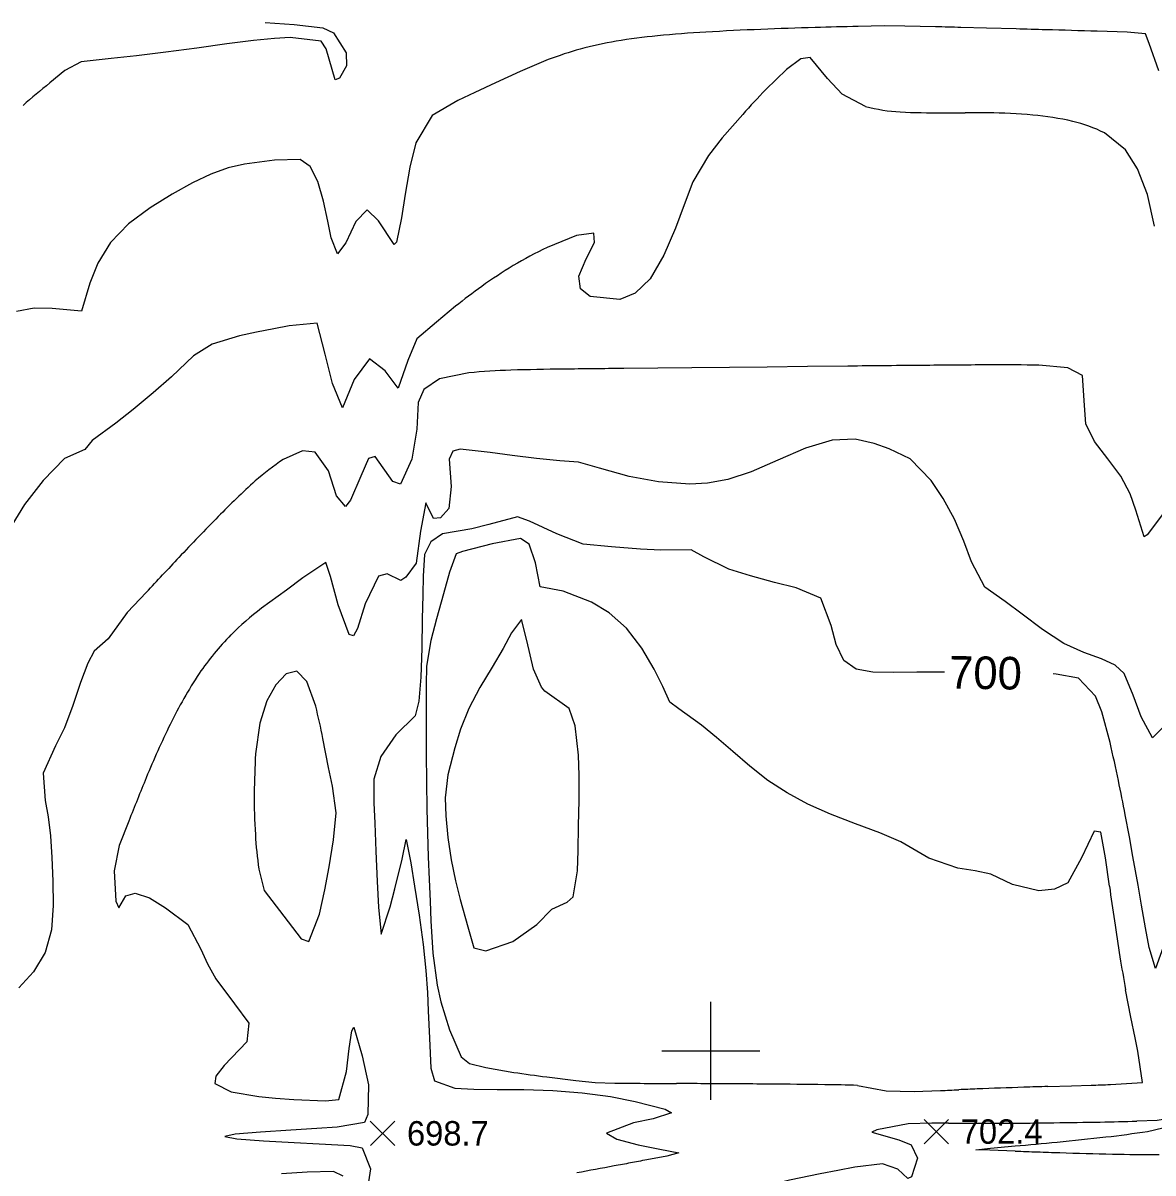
# Model space of a CAD drawing. Extents: x 2566079 to 2571326, y 424054 to 426896.
# Drawn here: x 2566578 to 2567271, y 424925 to 425631 of the extents above; entities that cross this region are included whole.
import ezdxf

# ---------------------------------------------------------------- set-up
doc = ezdxf.new("R2010")
doc.units = 0
for name, color, linetype in [('Contour_ADS_Label_Major', 7, 'Continuous'), ('Contour_ADS_Major', 7, 'Continuous'), ('Contour_ADS_Minor', 7, 'Continuous'), ('Contour_ADS_Spot_Elevation', 7, 'Continuous'), ('Contour_ADS_Tick', 7, 'Continuous')]:
    doc.layers.add(name, color=color, linetype=linetype)

# ---------------------------------------------------------------- blocks, each defined once
blk = doc.blocks.new('S890')
at = {"layer": 'Contour_ADS_Tick'}
for p, q in [((0, -0.5), (0, 0.5)), ((-0.5, 0), (0.5, 0))]:
    blk.add_line(p, q, dxfattribs=at)
blk = doc.blocks.new('S750')
at = {"layer": 'Contour_ADS_Spot_Elevation'}
for p, q in [((-0.5, 0.498), (0.5, -0.498)), ((-0.498, -0.5), (0.498, 0.5))]:
    blk.add_line(p, q, dxfattribs=at)

msp = doc.modelspace()

# ---------------------------------------------------------------- linework, layer by layer
at = {"layer": 'Contour_ADS_Major'}
for points in [[(2566726.44, 425630.92), (2566744.39, 425629.75), (2566761.94, 425627.82), (2566768.5, 425624.68), (2566776.31, 425612.3), (2566776.46, 425604.34), (2566772.04, 425596.78), (2566769.46, 425595.77), (2566764.01, 425614.94), (2566760.9, 425619.46), (2566741.87, 425621.82), (2566732.19, 425621.21), (2566719.3, 425619.91), (2566703.05, 425617.83), (2566684.65, 425615.31), (2566665.65, 425612.77), (2566647.59, 425610.59), (2566632, 425608.85), (2566613.63, 425606.79), (2566603.62, 425601.53), (2566594.32, 425593.88)], [(2567143.42, 425232.39), (2567142.83, 425232.39), (2567126.47, 425232.29), (2567111.9, 425232.14), (2567099.34, 425232.29), (2567089.13, 425234.18), (2567081.63, 425239.56), (2567076.91, 425249.32), (2567073.89, 425261), (2567067.55, 425277.73), (2567052.32, 425284.1), (2567039.07, 425287.44), (2567024.27, 425291.39), (2567011.04, 425295.55), (2566995.66, 425303.1), (2566987.93, 425307.51), (2566969.32, 425307.23), (2566956.79, 425307.76), (2566938.98, 425309.26), (2566921.63, 425310.99), (2566905.57, 425317.18), (2566888.76, 425325.1), (2566881.32, 425327.63), (2566863.83, 425323.05), (2566853.39, 425320.26), (2566835.3, 425317.15), (2566828.21, 425312.4), (2566824.2, 425304.54), (2566823.49, 425291.28), (2566823.17, 425279.73), (2566822.88, 425264.81), (2566822.59, 425247.05), (2566822, 425229.21), (2566820.75, 425214.58), (2566818.65, 425205.61), (2566806.79, 425193.97), (2566797.46, 425180.71), (2566793.28, 425166.74), (2566793.29, 425152.22), (2566793.77, 425139.67), (2566794.45, 425122.48), (2566795.22, 425103.88), (2566795.98, 425088.07), (2566797.72, 425071.69), (2566803.16, 425088.28), (2566806.13, 425099.33), (2566810.5, 425117.62), (2566813.11, 425129.77), (2566815.89, 425115.45), (2566818.25, 425101.07), (2566821.04, 425083.3), (2566823.53, 425065.2), (2566825.17, 425049.23), (2566826.1, 425035.74), (2566826.63, 425024.49), (2566827.37, 425007.83), (2566828.21, 424989.43), (2566830.37, 424981.63), (2566842.96, 424977.12), (2566854.51, 424976.51), (2566868.85, 424976.38), (2566885.31, 424976.24), (2566903.02, 424975.68), (2566921.06, 424974.3), (2566938.39, 424971.89), (2566953.58, 424968.98), (2566971.94, 424964.3), (2566975.81, 424961.99), (2566964.6, 424958.32), (2566952.45, 424955.91), (2566935.89, 424949.4), (2566942.26, 424945.74), (2566955.41, 424942.35), (2566968.71, 424939.7), (2566980.36, 424937.4), (2566972.94, 424935.36), (2566960.63, 424933.08)], [(2566757.54, 425211.41), (2566752.16, 425226.73), (2566745.93, 425232.98), (2566739.35, 425231.4), (2566733.04, 425224.64), (2566727.56, 425214.74), (2566723.3, 425201.03), (2566720.62, 425182.19), (2566720.62, 425182.19)], [(2567244.96, 425189.11), (2567240.01, 425208.04), (2567236.07, 425217.72), (2567225.66, 425228.76), (2567211.81, 425231.21), (2567210.08, 425231.29)], [(2566722.68, 425111.49), (2566725.91, 425098.32), (2566738.05, 425082.69), (2566748.58, 425068.74), (2566753.3, 425067.1), (2566759.92, 425083.86), (2566763.22, 425098.83), (2566765.88, 425112.88), (2566768.55, 425129.38), (2566770.11, 425146.13), (2566767.77, 425162.44), (2566765.35, 425173.87), (2566761.94, 425191.73)], [(2567329.12, 425145.83), (2567324.53, 425131.31), (2567319.01, 425116.32), (2567310.81, 425099.77), (2567304.32, 425085.2), (2567298.68, 425066.93), (2567296.97, 425065.26), (2567287, 425081.24), (2567278.53, 425066.56), (2567272.79, 425050.6), (2567268.93, 425063.35), (2567266.79, 425075.48), (2567264.35, 425089.33), (2567262.15, 425101.66), (2567258.93, 425119.34), (2567256.9, 425131.23), (2567254.31, 425144.82)]]:
    msp.add_lwpolyline(points, dxfattribs=at)
for centre, radius, start, end in [((2567135.74, 424935.15), 852.68, 129.41718, 130.8578), ((2566386.09, 425118.03), 383.01, 11.09426, 14.11128), ((2566333.83, 424976.68), 935.56, 11.66283, 13.12386), ((2567463.35, 425143.37), 743.74, 177.00782, 178.87264), ((2565807.82, 424864.24), 1473.46, 10.97759, 11.81021), ((2567070.74, 425155.99), 350.99, 179.67234, 183.81002), ((2566947.79, 425145.15), 227.61, 183.14245, 188.50367), ((2567959.66, 419478.51), 5545.3, 100.5879, 100.82923), ((2568351.49, 417377.12), 7682.9, 100.505369, 100.580769), ((2571254.73, 401707.86), 23618.85, 100.475086, 100.499608)]:
    msp.add_arc(centre, radius, start, end, dxfattribs=at)
at = {"layer": 'Contour_ADS_Minor'}
msp.add_line((2566739.59, 425282.7), (2566724.21, 425271.58), dxfattribs=at)
for points in [[(2567137.83, 425628.37), (2567119, 425628.84), (2567106.35, 425628.91), (2567090.32, 425628.6)], [(2567187.34, 425627.03), (2567169.06, 425627.53), (2567153.44, 425627.95)], [(2567274.88, 425601.39), (2567269.04, 425618.18), (2567266.65, 425623.97), (2567255.56, 425625.02), (2567237.07, 425625.63)], [(2566900.26, 425608.21), (2566882.94, 425600.93), (2566867.93, 425593.93), (2566855.24, 425588.08), (2566844.68, 425583.15), (2566829, 425573.96), (2566818.89, 425557.16), (2566815.28, 425542.32), (2566812.42, 425525.71), (2566810.24, 425511.05), (2566807.16, 425496.2), (2566805.69, 425494.7), (2566796.05, 425509.34), (2566789.19, 425516.11), (2566782.18, 425508.99), (2566775.94, 425495.72), (2566770.99, 425489.07), (2566767.04, 425498.89), (2566764.9, 425509.11), (2566762.28, 425521.43), (2566758.82, 425533.48), (2566754.14, 425542.59), (2566747.97, 425546.88), (2566732.21, 425546.57), (2566713.8, 425544.15), (2566703.81, 425541.82), (2566693.26, 425537.99), (2566681.9, 425532.59), (2566669.44, 425525.69), (2566655.91, 425517.31), (2566642.71, 425507.42), (2566631.56, 425495.96), (2566623.77, 425483.23), (2566618.91, 425471), (2566613.88, 425453.8), (2566595.73, 425455.47), (2566584.84, 425455.66), (2566573.88, 425453.74)], [(2567094.98, 425579.48), (2567080.63, 425587.1), (2567071.66, 425596.68), (2567060.97, 425609.43), (2567055.13, 425608.71), (2567046.4, 425602.17), (2567033.76, 425589.83)], [(2567019.56, 425574.61), (2567007.01, 425560.17), (2566998.56, 425549.37), (2566988.98, 425533.19), (2566983.58, 425519.12), (2566978.27, 425504.76), (2566971.2, 425488.21), (2566962.84, 425473.78), (2566953.66, 425464.85), (2566944.11, 425460.96), (2566925.98, 425462.83), (2566920.01, 425467.6), (2566918.93, 425475.39), (2566923.48, 425485.92), (2566928.71, 425496.02), (2566928.25, 425501.79), (2566917.56, 425500.36), (2566899.5, 425492.95)], [(2567272.24, 425505.93), (2567267.97, 425525.4), (2567261.84, 425541.25), (2567254.34, 425552.81), (2567241.47, 425563.26)], [(2566843.35, 425456.87), (2566831.56, 425447.15), (2566819.53, 425436.95), (2566814.06, 425423.56), (2566808.08, 425406.71), (2566800.08, 425417.22), (2566790.54, 425424.66), (2566781.14, 425412.03), (2566773.93, 425394.56), (2566767.86, 425409.45), (2566763.37, 425427.47), (2566758.52, 425446.46), (2566741.3, 425444.89), (2566731.81, 425443.13), (2566721.14, 425441.05), (2566710.68, 425438.75), (2566693.96, 425433.53), (2566682.56, 425426.41), (2566668.97, 425413.66), (2566657.78, 425403.82), (2566645.43, 425393.52), (2566634.81, 425385.23), (2566620.42, 425374.45), (2566615.9, 425369.07), (2566603.46, 425363.52), (2566590.35, 425349.93), (2566578.9, 425335.29), (2566571.09, 425322.54)], [(2567083.96, 425420.13), (2567059.27, 425419.87), (2567034.58, 425419.61), (2566988.4, 425419.14), (2566946.57, 425418.71)], [(2567279.52, 425332.34), (2567267.72, 425316.68), (2567265.92, 425315.41), (2567260.86, 425331.75), (2567257.33, 425341.84), (2567251.6, 425352.7), (2567243.51, 425363.3), (2567235.36, 425373.8), (2567230.07, 425384.65), (2567229.35, 425395.95), (2567227.99, 425414.49), (2567219.15, 425419), (2567201.23, 425420.72)], [(2566851.47, 425416.02), (2566833.44, 425412.3), (2566823.87, 425405.89), (2566820.37, 425397.77), (2566819.6, 425381.51), (2566816.5, 425362.99), (2566809.66, 425347.64), (2566804.93, 425349.32), (2566794.02, 425364.63), (2566789.9, 425363.49), (2566785.16, 425352.56), (2566778.95, 425337.82), (2566775.79, 425334.1), (2566770.33, 425340.55), (2566765.48, 425355.82), (2566757.22, 425367.36), (2566749.46, 425368.08), (2566737.67, 425362.9)], [(2567283.08, 425204.34), (2567271.05, 425192.14), (2567264.09, 425205.02), (2567259.19, 425218.26), (2567253.55, 425231.5), (2567248.16, 425236.72), (2567239.79, 425240.58), (2567228.94, 425244.43), (2567216.5, 425250.04), (2567203.44, 425258.45), (2567191.03, 425267.87), (2567180.67, 425275.82), (2567168.13, 425284.57), (2567159.9, 425300.09), (2567155.2, 425312.72), (2567149.48, 425326.28), (2567142.53, 425339), (2567135.1, 425349.87), (2567122.21, 425363.23), (2567109.45, 425369.3), (2567100.22, 425372.73), (2567088.53, 425375.23), (2567074.42, 425374.66), (2567058.18, 425369.73), (2567041.1, 425362.35), (2567024.78, 425355.27), (2567010.44, 425350.64), (2566998, 425348.34), (2566987.05, 425347.68), (2566967.91, 425349.1), (2566949.88, 425352.41), (2566931.63, 425357.57), (2566918.73, 425361.13), (2566907.38, 425362.1), (2566892.96, 425363.49), (2566878, 425365.26), (2566864.68, 425367.24), (2566846.11, 425369.24), (2566841.67, 425368.05), (2566839.36, 425363.06), (2566840.61, 425346.23), (2566839.13, 425332.77), (2566834.16, 425327.03), (2566829.75, 425326.59), (2566825.11, 425336.28), (2566821.78, 425318.85), (2566819.15, 425299.15), (2566812.77, 425290.63), (2566809.72, 425288.61), (2566801.42, 425292.6), (2566796.03, 425291.33), (2566787.92, 425274.39), (2566783.11, 425259.19), (2566780.74, 425254.69), (2566777.99, 425255.41), (2566771.36, 425273.62), (2566766.56, 425291.13), (2566763.77, 425299.68), (2566749.67, 425290.26), (2566739.59, 425282.7)], [(2567244.55, 425101.15), (2567242.16, 425118.38), (2567239.2, 425134.17), (2567235.14, 425134.71), (2567227.36, 425118.5), (2567219.12, 425103.13), (2567210.92, 425099.22), (2567201.24, 425098.19), (2567185.13, 425102.08), (2567171.72, 425108.39), (2567162.23, 425110.4), (2567151.64, 425112.09), (2567133.73, 425118.13), (2567116.52, 425128.26), (2567103.68, 425133.74), (2567088.72, 425139.34), (2567073.49, 425145.18), (2567059.49, 425151.39), (2567046.77, 425158.22), (2567035, 425165.93), (2567023.91, 425174.64), (2567013.42, 425183.7), (2567003.49, 425192.31), (2566994.21, 425199.77), (2566980.26, 425209.95), (2566974.9, 425214.02), (2566970.55, 425223.63), (2566965.26, 425234.17), (2566957.71, 425247.01), (2566948.31, 425259.28), (2566937.61, 425268.69), (2566926.75, 425275.24), (2566909.42, 425282.08), (2566895.22, 425284.71), (2566892.46, 425299.35), (2566888.49, 425310.99), (2566883.27, 425314.39), (2566865.79, 425311.05), (2566847.51, 425306.43), (2566843.78, 425304.91), (2566839.7, 425293.64), (2566839.7, 425293.64)], [(2566839.7, 425293.64), (2566835.9, 425280.41), (2566831.72, 425265.02), (2566828.25, 425251.73), (2566825.42, 425236.11), (2566825.33, 425224.68), (2566825.3, 425214.14), (2566825.27, 425199.54), (2566825.3, 425182.44), (2566825.44, 425164.9), (2566825.73, 425148.59), (2566826.13, 425133.47), (2566826.62, 425119.05), (2566827.15, 425105.05), (2566827.69, 425091.81), (2566828.2, 425079.86), (2566829.37, 425059.97), (2566832.16, 425040.29), (2566834.36, 425030.08), (2566839.56, 425012.94), (2566846.84, 424996.26), (2566851.98, 424992.27), (2566861.86, 424989.7), (2566879.04, 424986.81)], [(2566653.65, 425281.4), (2566641.89, 425268.99), (2566630.24, 425252.83), (2566621.6, 425245.34), (2566617.65, 425237.93), (2566613.27, 425226.07), (2566608.49, 425211.85), (2566603.3, 425198.13), (2566597.89, 425187.09), (2566590.36, 425170.34), (2566591.53, 425153.66), (2566593.43, 425143.62), (2566594.79, 425131.87), (2566595.61, 425118.6), (2566596.16, 425104.2), (2566596.45, 425089.12), (2566595.37, 425074.21), (2566591.56, 425060.38), (2566584.3, 425048.46), (2566575.46, 425038.76)], [(2566642.87, 425140.99), (2566636.88, 425125.92), (2566633.81, 425110.42), (2566634.95, 425091.78), (2566636.65, 425087.66), (2566641.1, 425095.03), (2566646.7, 425096.79), (2566655.45, 425093.79), (2566665.38, 425087.82), (2566679.04, 425077.63), (2566687.13, 425062.41), (2566691.2, 425053.43), (2566696.2, 425044.22), (2566707.77, 425028.85), (2566716.52, 425017.08), (2566715.22, 425005.44), (2566701.46, 424990.93), (2566696.18, 424984.53), (2566695.67, 424979.93), (2566705.66, 424974.78), (2566722.6, 424971.91), (2566732.9, 424970.9), (2566744.11, 424970.08), (2566763.52, 424969.34), (2566771.7, 424970.25), (2566776.36, 424987.33), (2566778.04, 425001.44), (2566779.8, 425012.38), (2566780.95, 425014.47), (2566786.1, 424996.98), (2566790.02, 424979.09), (2566789.5, 424960.95), (2566787.42, 424956.1), (2566770.71, 424953.13), (2566758.27, 424952.34), (2566742.21, 424951.4), (2566723.69, 424950.2), (2566708.07, 424948.82), (2566701.83, 424947.38), (2566709.19, 424945.98), (2566725.6, 424944.73), (2566744.28, 424943.7), (2566759.64, 424942.94), (2566778.69, 424941.93), (2566785.98, 424940.52), (2566791.17, 424927.69), (2566788.56, 424910.25)], [(2567245.14, 424979.35), (2567264.96, 424980.62), (2567262.05, 424999.72), (2567260.34, 425007.95), (2567257.75, 425020.69), (2567254.52, 425037.52)], [(2566899.32, 424984.03), (2566917.08, 424981.87), (2566929.01, 424980.68), (2566941.12, 424980.2)], [(2567089.94, 424978.82), (2567107.51, 424975.46), (2567124.78, 424975.01), (2567140.91, 424975.66)], [(2567206.69, 424978.12), (2567221.4, 424978.59), (2567233.27, 424978.97)], [(2567267.96, 424950.61), (2567282.52, 424953.93), (2567288.21, 424956.79), (2567289.19, 424959.98), (2567273.93, 424957.24), (2567261.38, 424956.83)], [(2567135.59, 424955.58), (2567121.03, 424955.31), (2567101.89, 424951.58), (2567098.74, 424950.18), (2567115.43, 424945.39), (2567123.01, 424942.33), (2567126.82, 424934.16), (2567123.13, 424922.75), (2567120.87, 424921.67), (2567114.66, 424927.34), (2567105.41, 424930.73), (2567088.41, 424928.68), (2567077.97, 424926.62), (2567067.09, 424924.45), (2567048.2, 424920.68), (2567033.27, 424916.95), (2567023.81, 424913.57), (2567012.1, 424903.18), (2566999.26, 424893.79), (2566986.41, 424884.54), (2566971.69, 424874.69), (2566958.06, 424864.54), (2566944.29, 424852.07)], [(2567186.76, 424938.46), (2567171.19, 424938.99), (2567162.5, 424939.31), (2567171.6, 424940.3), (2567186.67, 424941.64)], [(2566774.42, 424923.13), (2566768.42, 424926.01), (2566752.23, 424925.63), (2566736.54, 424924.63)]]:
    msp.add_lwpolyline(points, dxfattribs=at)
msp.add_lwpolyline([(2566896.02, 425223.22), (2566891.12, 425234.16), (2566887.18, 425251.85), (2566883.84, 425264.58), (2566877.74, 425256.58), (2566872.57, 425246.84), (2566865.73, 425235.35), (2566858.24, 425222.88), (2566851.46, 425210.02), (2566846.41, 425197.4), (2566842.9, 425185.89), (2566838.63, 425169.38), (2566837.04, 425155.17), (2566837.42, 425144.12), (2566838.62, 425130.89), (2566840.61, 425117.13), (2566843.3, 425104.27), (2566846.24, 425092.91), (2566850.81, 425076.12), (2566854.62, 425063.29), (2566861.83, 425061.37), (2566878.57, 425067.03), (2566893.28, 425077.59), (2566902.4, 425087.03), (2566911.86, 425091.17), (2566915.5, 425094.52), (2566918.26, 425110.44), (2566918.51, 425122.95), (2566918.81, 425137.97), (2566919.1, 425153.89), (2566919.15, 425168.87), (2566918.81, 425181.41), (2566916.82, 425199.37), (2566913.12, 425210), (2566898.15, 425220.7), (2566896.02, 425223.22)], close=True, dxfattribs=at)
for centre, radius, start, end in [((2567168.52, 422185.7), 3443.78, 91.30114, 91.74002), ((2566790.91, 412444.04), 13188.89, 88.424861, 88.4927), ((2567006.79, 425222.81), 401.95, 95.65334, 99.29269), ((2567045.23, 424808.64), 817.89, 93.39026, 95.47508), ((2567097.96, 423897.08), 1730.97, 92.22481, 93.34826), ((2567153.99, 422549.64), 3079.58, 91.67551, 92.29338), ((2566494.23, 399952.62), 25683.76, 88.412822, 88.453617), ((2566771.35, 409901.08), 15731.44, 88.303528, 88.418119), ((2566981.52, 425394.98), 228.19, 105.67597, 110.86035), ((2566983.38, 425376.2), 246.79, 99.68013, 104.91422), ((2567382.89, 425249.86), 487.31, 135.76188, 138.20946), ((2567123.55, 425690.06), 114.21, 255.51134, 266.26794), ((2567143.3, 426271.61), 696.05, 267.76174, 269.90088), ((2567147.36, 426795.94), 1220.39, 269.75292, 270.41067), ((2567163.87, 425049.5), 526.14, 89.31834, 90.84513), ((2567164.08, 425188.39), 387.26, 85.04502, 89.10503), ((2567181.33, 425391.6), 183.31, 77.16965, 84.93072), ((2567202.16, 425485.58), 87.06, 63.158, 76.80004), ((2567000.46, 425280.58), 235.15, 115.42635, 121.16527), ((2567031.57, 425228.75), 295.6, 121.12666, 125.60708), ((2567079.88, 425161.34), 378.53, 125.61127, 128.67252), ((2566890.06, 425017.78), 400.1, 91.83421, 95.53428), ((2566941.61, 422874.46), 2544.04, 90.72622, 91.44975), ((2567158.23, 405023.77), 20396.04, 90.594606, 90.699114), ((2567575.99, 377810.81), 47611.87, 90.534589, 90.592114), ((2567229.62, 415270.61), 10150.46, 90.323425, 90.552378), ((2567177.63, 424029.08), 1391.84, 89.02838, 90.21852), ((2566824.96, 425231.6), 157.67, 123.61657, 131.49805), ((2567074.55, 424957.58), 528.31, 132.08094, 135.50858), ((2567825.02, 424221.3), 1579.64, 135.53404, 136.79568), ((2568384.03, 423694.5), 2347.77, 136.76424, 137.12062), ((2564272.78, 427518.15), 3266.74, 316.78763, 317.04363), ((2566848.41, 425110.75), 203.2, 127.67739, 134.70744), ((2566836, 425127.95), 182.28, 135.737, 145.37077), ((2566926.31, 425074.13), 287.26, 146.7748, 153.93742), ((2567183.91, 424948.59), 573.82, 153.97789, 157.56225), ((2571012.12, 423406.76), 4700.84, 158.00158, 158.35108), ((2571062.23, 425635.9), 3854.95, 187.97366, 188.29406), ((2568759.1, 425301.63), 1527.69, 188.3488, 189.19013), ((2568330.06, 425234.98), 1093.52, 189.33319, 190.40323), ((2567018.89, 425931.64), 955.13, 261.58052, 262.80847), ((2566996.48, 430788.11), 5808.17, 269.453883, 269.657397), ((2567028.75, 436090.38), 11110.54, 269.654506, 269.742742), ((2566822.94, 396838.45), 28141.93, 89.647719, 89.682556), ((2566887.42, 405310.75), 19669.4, 89.567822, 89.683789), ((2566984.52, 418118.5), 6861.28, 89.286858, 89.571961), ((2567052.43, 423698.68), 1280.69, 88.32162, 89.2175), ((2567217.37, 425661.33), 682.55, 271.33514, 272.33208), ((2566697.09, 435500.24), 10533.94, 272.414714, 272.475906), ((2567327.57, 420915.68), 4064.24, 92.31513, 92.47372), ((2567404.56, 418679.78), 6301.45, 91.933217, 92.193339), ((2567477.76, 416445.4), 8537.03, 91.819558, 91.918336), ((2567140.67, 424022.34), 933.25, 89.68842, 90.31157), ((2567150.82, 446643.61), 21688.03, 269.986594, 270.013408), ((2567153.96, 437372.58), 12417, 270.008922, 270.126264), ((2567159.37, 428769.05), 3813.51, 270.32976, 270.76865), ((2567155.05, 429362.86), 4407.32, 270.72124, 271.09114), ((2567183.86, 427988.52), 3032.68, 271.04149, 271.46479), ((2567177.28, 425526.98), 583.46, 276.41251, 278.94145), ((2566824.48, 428988.65), 4063.18, 275.11407, 275.47916), ((2567054.5, 426597.36), 1660.86, 275.45705, 276.49731), ((2568115.72, 452930.04), 28006.99, 268.099211, 268.127172), ((2567366.37, 429768.05), 4832.89, 268.03217, 268.19421), ((2567322.02, 428314.92), 3379.08, 268.16941, 268.71899), ((2567274.47, 426159.89), 1223.53, 268.68932, 270.02544)]:
    msp.add_arc(centre, radius, start, end, dxfattribs=at)

# ---------------------------------------------------------------- block references
at = {"layer": 'Contour_ADS_Spot_Elevation', "xscale": 15, "yscale": 15}
for p in [(2567138.35, 424950.47), (2566798.54, 424949.39)]:
    msp.add_blockref('S750', p, dxfattribs=at)
at = {"layer": 'Contour_ADS_Tick', "xscale": 60, "yscale": 60}
msp.add_blockref('S890', (2567000, 425000), dxfattribs=at)

# ---------------------------------------------------------------- texts
at = {"layer": 'Contour_ADS_Label_Major'}
msp.add_text('700', height=20, rotation=359.0607, dxfattribs=at).set_placement((2567146.07, 425222.35))
at = {"layer": 'Contour_ADS_Spot_Elevation'}
for s, p in [('702.4', (2567153.35, 424942.97)), ('698.7', (2566813.54, 424941.89))]:
    msp.add_text(s, height=15, dxfattribs=at).set_placement(p)

doc.saveas('drawing.dxf')
